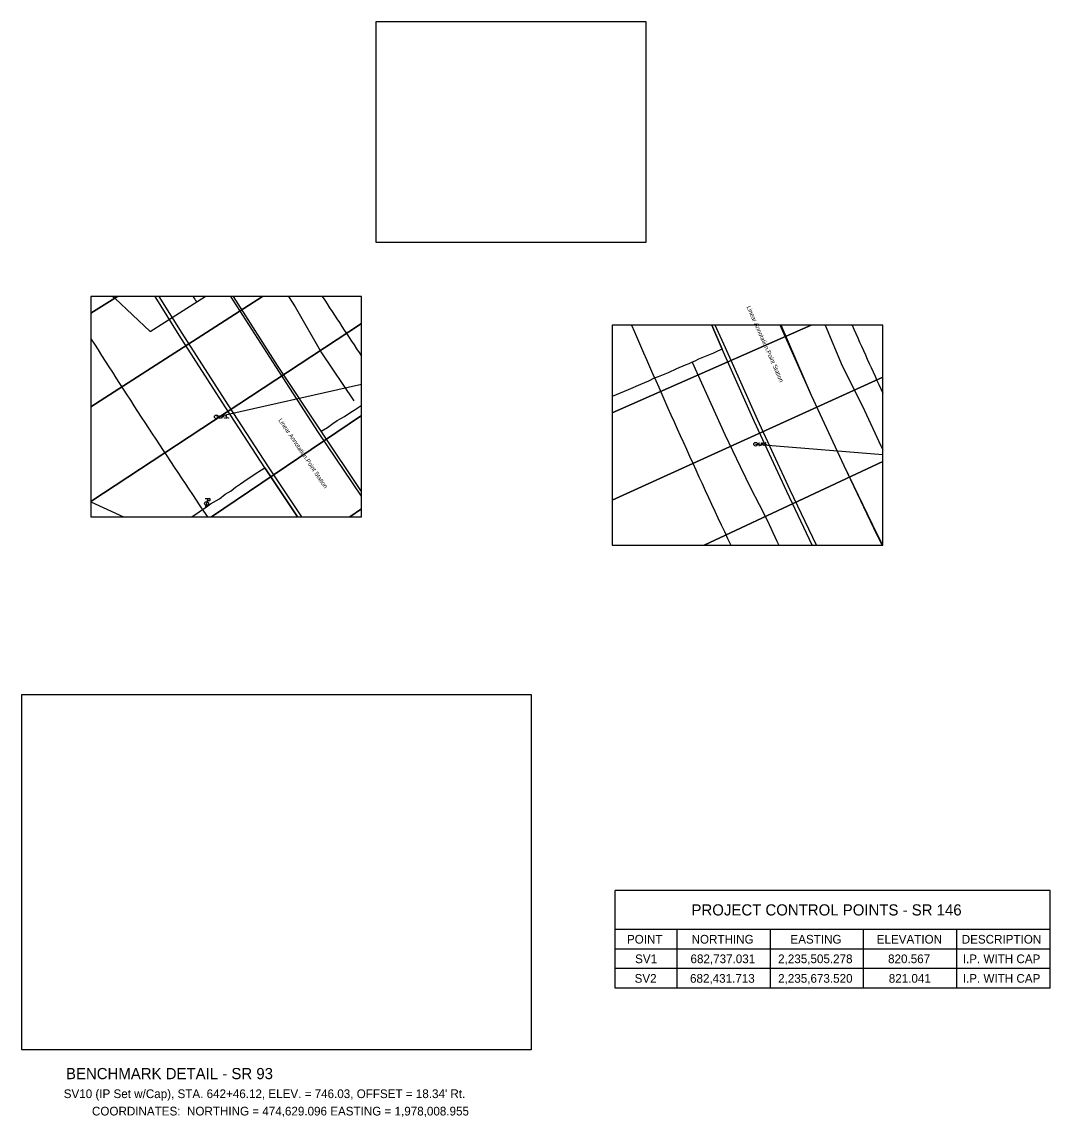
# Model space of a CAD drawing. Extents: x 0 to 2009, y -63 to 801.
# Drawn here: x 305.4 to 636.3, y 448.3 to 801 of the extents above; entities that cross this region are included whole.
import ezdxf

# ---------------------------------------------------------------- set-up
doc = ezdxf.new("R2010")
doc.units = 0
for name, color, linetype in [('Default', 7, 'Continuous'), ('DR_X_Ditch', 7, 'Continuous'), ('GE_P_Alignment', 7, 'Continuous'), ('GE_X_Alignment', 7, 'Continuous'), ('GE_X_Cells', 7, 'Continuous'), ('PF_P_Sta_Elev_Text', 7, 'Continuous'), ('PF_X_Text', 7, 'Continuous'), ('PV_X_Driveway', 7, 'Continuous'), ('RD_P_Cells', 7, 'Continuous'), ('RW_X_CL_100_Stations', 7, 'Continuous'), ('RW_X_CL_500_Stations', 7, 'Continuous'), ('SH_Data', 7, 'Continuous'), ('SN_X_Public', 7, 'Continuous'), ('ST_Text', 7, 'Continuous'), ('SV_P_Control_Cells_Set', 7, 'Continuous'), ('SV_X_Text_Name', 7, 'Continuous'), ('TX_P_1', 7, 'Continuous'), ('TX_P_Misc', 7, 'Continuous'), ('UT_X_Telecom', 7, 'Continuous'), ('XS_P_Finished_Grade', 7, 'Continuous'), ('XS_P_Pavt_Surface', 7, 'Continuous')]:
    doc.layers.add(name, color=color, linetype=linetype)

msp = doc.modelspace()

# ---------------------------------------------------------------- linework, layer by layer
at = {"layer": 'DR_X_Ditch'}
msp.add_lwpolyline([(305.36, 584.42), (469.27, 584.42), (469.27, 469.95), (305.36, 469.95)], close=True, dxfattribs=at)
at = {"layer": 'GE_P_Alignment'}
for points in [[(394.06, 641.65), (383.49, 657.42), (369.82, 678.5), (355.95, 700.12), (348.27, 712.56)], [(414.66, 649.71), (401.63, 669.22), (387.65, 690.38), (374.21, 711.42), (373.48, 712.56)], [(559.68, 632.46), (551.57, 649.72), (541.01, 672.42), (530.76, 695.62), (527.41, 703.37)], [(582.41, 632.49), (580.75, 635.83), (569.94, 658.08), (559.48, 680.72), (549.69, 703.37)]]:
    msp.add_lwpolyline(points, dxfattribs=at)
at = {"layer": 'GE_X_Alignment'}
for p, q in [((365.22, 647.48), (364.42, 644.48)), ((365.05, 646.84), (365.64, 646.84)), ((365.22, 647.48), (365.64, 647.48))]:
    msp.add_line(p, q, dxfattribs=at)
msp.add_circle((364.79, 645.88), 0.65, dxfattribs=at)
msp.add_arc((365.65, 647.16), 0.319, 268.8767, 91.1233, dxfattribs=at)
at = {"layer": 'GE_X_Cells'}
for p, q in [((496.25, 489.85), (496.25, 521.35)), ((636.25, 521.35), (496.25, 521.35)), ((636.25, 489.85), (636.25, 521.35)), ((636.25, 508.75), (496.25, 508.75)), ((516.25, 489.85), (516.25, 508.75)), ((546.25, 489.85), (546.25, 508.75)), ((576.25, 489.85), (576.25, 508.75)), ((606.25, 489.85), (606.25, 508.75)), ((636.25, 502.45), (496.25, 502.45)), ((636.25, 496.15), (496.25, 496.15)), ((636.25, 489.85), (496.25, 489.85))]:
    msp.add_line(p, q, dxfattribs=at)
at = {"layer": 'PF_P_Sta_Elev_Text'}
for points in [[(368.95, 674.17), (369.13, 674.17)], [(368.95, 674.17), (369.13, 674.17)], [(369.04, 673.37), (369.04, 674.17)], [(369.04, 673.37), (369.04, 674.17)], [(369.82, 673.37), (369.82, 674.17), (370.09, 674.17), (370.11, 674.16), (370.15, 674.15), (370.17, 674.14), (370.19, 674.13), (370.21, 674.1), (370.22, 674.06), (370.24, 674.01), (370.24, 673.94), (370.23, 673.91), (370.22, 673.88), (370.2, 673.83), (370.18, 673.81), (370.16, 673.8), (370.13, 673.79), (370.09, 673.78), (369.82, 673.78)], [(369.82, 673.37), (369.82, 674.17), (370.09, 674.17), (370.11, 674.16), (370.15, 674.15), (370.17, 674.14), (370.19, 674.13), (370.21, 674.1), (370.22, 674.06), (370.24, 674.01), (370.24, 673.94), (370.23, 673.91), (370.22, 673.88), (370.2, 673.83), (370.18, 673.81), (370.16, 673.8), (370.13, 673.79), (370.09, 673.78), (369.82, 673.78)], [(371.33, 674.11), (371.32, 674.13), (371.3, 674.14), (371.25, 674.16), (371.19, 674.17), (371.15, 674.17), (371.13, 674.17), (371.06, 674.15), (371, 674.11), (370.96, 674.06), (370.95, 674.01), (370.95, 673.98), (370.96, 673.93), (371, 673.88), (371.31, 673.69), (371.33, 673.67), (371.34, 673.64), (371.35, 673.6), (371.35, 673.57), (371.35, 673.53), (371.34, 673.5), (371.33, 673.47), (371.32, 673.45), (371.31, 673.43), (371.29, 673.41), (371.28, 673.4), (371.26, 673.38), (371.24, 673.38), (371.19, 673.37), (371.11, 673.37), (371.06, 673.38), (370.99, 673.43), (370.95, 673.47)], [(371.33, 674.11), (371.32, 674.13), (371.3, 674.14), (371.25, 674.16), (371.19, 674.17), (371.15, 674.17), (371.13, 674.17), (371.06, 674.15), (371, 674.11), (370.96, 674.06), (370.95, 674.01), (370.95, 673.98), (370.96, 673.93), (371, 673.88), (371.31, 673.69), (371.33, 673.67), (371.34, 673.64), (371.35, 673.6), (371.35, 673.57), (371.35, 673.53), (371.34, 673.5), (371.33, 673.47), (371.32, 673.45), (371.31, 673.43), (371.29, 673.41), (371.28, 673.4), (371.26, 673.38), (371.24, 673.38), (371.19, 673.37), (371.11, 673.37), (371.06, 673.38), (370.99, 673.43), (370.95, 673.47)], [(368.95, 673.37), (369.13, 673.37)], [(368.95, 673.37), (369.13, 673.37)], [(369.52, 673.48), (369.55, 673.48), (369.56, 673.47), (369.58, 673.44), (369.58, 673.41), (369.56, 673.38), (369.55, 673.37), (369.52, 673.37), (369.5, 673.38), (369.49, 673.41), (369.49, 673.44), (369.5, 673.47), (369.52, 673.48)], [(369.52, 673.48), (369.55, 673.48), (369.56, 673.47), (369.58, 673.44), (369.58, 673.41), (369.56, 673.38), (369.55, 673.37), (369.52, 673.37), (369.5, 673.38), (369.49, 673.41), (369.49, 673.44), (369.5, 673.47), (369.52, 673.48)], [(370.64, 673.48), (370.67, 673.48), (370.69, 673.47), (370.7, 673.44), (370.7, 673.41), (370.69, 673.38), (370.67, 673.37), (370.64, 673.37), (370.63, 673.38), (370.61, 673.41), (370.61, 673.44), (370.63, 673.47), (370.64, 673.48)], [(370.64, 673.48), (370.67, 673.48), (370.69, 673.47), (370.7, 673.44), (370.7, 673.41), (370.69, 673.38), (370.67, 673.37), (370.64, 673.37), (370.63, 673.38), (370.61, 673.41), (370.61, 673.44), (370.63, 673.47), (370.64, 673.48)], [(371.73, 673.48), (371.76, 673.48), (371.78, 673.47), (371.8, 673.44), (371.8, 673.41), (371.78, 673.38), (371.76, 673.37), (371.73, 673.37), (371.72, 673.38), (371.7, 673.41), (371.7, 673.44), (371.72, 673.47), (371.73, 673.48)], [(371.73, 673.48), (371.76, 673.48), (371.78, 673.47), (371.8, 673.44), (371.8, 673.41), (371.78, 673.38), (371.76, 673.37), (371.73, 673.37), (371.72, 673.38), (371.7, 673.41), (371.7, 673.44), (371.72, 673.47), (371.73, 673.48)], [(542.51, 665.38), (542.69, 665.38)], [(542.51, 665.38), (542.69, 665.38)], [(542.51, 664.58), (542.69, 664.58)], [(542.51, 664.58), (542.69, 664.58)], [(542.6, 664.58), (542.6, 665.38)], [(542.6, 664.58), (542.6, 665.38)], [(543.08, 664.69), (543.11, 664.69), (543.12, 664.67), (543.14, 664.65), (543.14, 664.62), (543.12, 664.59), (543.11, 664.58), (543.08, 664.58), (543.06, 664.59), (543.05, 664.62), (543.05, 664.65), (543.06, 664.67), (543.08, 664.69)], [(543.08, 664.69), (543.11, 664.69), (543.12, 664.67), (543.14, 664.65), (543.14, 664.62), (543.12, 664.59), (543.11, 664.58), (543.08, 664.58), (543.06, 664.59), (543.05, 664.62), (543.05, 664.65), (543.06, 664.67), (543.08, 664.69)], [(543.38, 664.58), (543.38, 665.38), (543.65, 665.38), (543.68, 665.37), (543.71, 665.36), (543.73, 665.35), (543.75, 665.33), (543.77, 665.3), (543.79, 665.27), (543.8, 665.22), (543.8, 665.15), (543.79, 665.12), (543.78, 665.08), (543.76, 665.04), (543.74, 665.02), (543.72, 665.01), (543.69, 664.99), (543.65, 664.99), (543.38, 664.99)], [(543.38, 664.58), (543.38, 665.38), (543.65, 665.38), (543.68, 665.37), (543.71, 665.36), (543.73, 665.35), (543.75, 665.33), (543.77, 665.3), (543.79, 665.27), (543.8, 665.22), (543.8, 665.15), (543.79, 665.12), (543.78, 665.08), (543.76, 665.04), (543.74, 665.02), (543.72, 665.01), (543.69, 664.99), (543.65, 664.99), (543.38, 664.99)], [(544.2, 664.69), (544.23, 664.69), (544.25, 664.67), (544.27, 664.65), (544.27, 664.62), (544.25, 664.59), (544.23, 664.58), (544.2, 664.58), (544.19, 664.59), (544.17, 664.62), (544.17, 664.65), (544.19, 664.67), (544.2, 664.69)], [(544.2, 664.69), (544.23, 664.69), (544.25, 664.67), (544.27, 664.65), (544.27, 664.62), (544.25, 664.59), (544.23, 664.58), (544.2, 664.58), (544.19, 664.59), (544.17, 664.62), (544.17, 664.65), (544.19, 664.67), (544.2, 664.69)], [(544.89, 665.32), (544.88, 665.33), (544.86, 665.35), (544.81, 665.37), (544.75, 665.38), (544.71, 665.38), (544.69, 665.38), (544.62, 665.36), (544.56, 665.32), (544.52, 665.27), (544.51, 665.22), (544.51, 665.18), (544.52, 665.13), (544.56, 665.09), (544.87, 664.9), (544.89, 664.87), (544.9, 664.85), (544.92, 664.81), (544.92, 664.77), (544.91, 664.74), (544.9, 664.71), (544.89, 664.68), (544.88, 664.65), (544.87, 664.64), (544.86, 664.62), (544.84, 664.6), (544.82, 664.59), (544.8, 664.58), (544.75, 664.58), (544.67, 664.58), (544.62, 664.59), (544.55, 664.64), (544.51, 664.67)], [(544.89, 665.32), (544.88, 665.33), (544.86, 665.35), (544.81, 665.37), (544.75, 665.38), (544.71, 665.38), (544.69, 665.38), (544.62, 665.36), (544.56, 665.32), (544.52, 665.27), (544.51, 665.22), (544.51, 665.18), (544.52, 665.13), (544.56, 665.09), (544.87, 664.9), (544.89, 664.87), (544.9, 664.85), (544.92, 664.81), (544.92, 664.77), (544.91, 664.74), (544.9, 664.71), (544.89, 664.68), (544.88, 664.65), (544.87, 664.64), (544.86, 664.62), (544.84, 664.6), (544.82, 664.59), (544.8, 664.58), (544.75, 664.58), (544.67, 664.58), (544.62, 664.59), (544.55, 664.64), (544.51, 664.67)], [(545.3, 664.69), (545.32, 664.69), (545.34, 664.67), (545.36, 664.65), (545.36, 664.62), (545.34, 664.59), (545.32, 664.58), (545.3, 664.58), (545.28, 664.59), (545.26, 664.62), (545.26, 664.65), (545.28, 664.67), (545.3, 664.69)], [(545.3, 664.69), (545.32, 664.69), (545.34, 664.67), (545.36, 664.65), (545.36, 664.62), (545.34, 664.59), (545.32, 664.58), (545.3, 664.58), (545.28, 664.59), (545.26, 664.62), (545.26, 664.65), (545.28, 664.67), (545.3, 664.69)]]:
    msp.add_lwpolyline(points, dxfattribs=at)
for centre in [(367.94, 673.77), (367.94, 673.77), (541.5, 664.98), (541.5, 664.98)]:
    msp.add_circle(centre, 0.6, dxfattribs=at)
at = {"layer": 'PF_X_Text'}
for points in [[(395.4, 641.65), (384.53, 658.06), (370.8, 679.15), (356.98, 700.71), (349.58, 712.56)], [(414.66, 648.15), (414.62, 648.21), (400.85, 668.8), (387.03, 690.02), (373.56, 711.02), (372.6, 712.56)], [(561.03, 632.46), (552.65, 650.14), (542.12, 672.9), (531.74, 696.02), (528.52, 703.37)], [(582.2, 632.46), (580.59, 635.73), (569.94, 658.08), (559.48, 680.72), (549.35, 703.37)]]:
    msp.add_lwpolyline(points, dxfattribs=at)
at = {"layer": 'RD_P_Cells'}
for points in [[(391.13, 712.56), (393.27, 709.19), (401.8, 694.46), (412.21, 678.92)], [(563.83, 703.37), (569.35, 690.2), (575.9, 677.28), (581.77, 664.49), (582.41, 663.15)]]:
    msp.add_lwpolyline(points, dxfattribs=at)
at = {"layer": 'RW_X_CL_100_Stations'}
for p, q in [((327.59, 707.2), (336.13, 712.56)), ((336.13, 712.56), (327.59, 707.2)), ((327.59, 677.06), (382.75, 712.56)), ((382.75, 712.56), (327.59, 677.06)), ((327.59, 707.2), (336.13, 712.56)), ((336.13, 712.56), (327.59, 707.2)), ((327.59, 677.06), (382.75, 712.56)), ((382.75, 712.56), (327.59, 677.06)), ((336.13, 712.56), (336.13, 712.56)), ((336.13, 712.56), (336.13, 712.56)), ((382.75, 712.56), (382.75, 712.56)), ((382.75, 712.56), (382.75, 712.56)), ((327.59, 707.2), (327.59, 707.2)), ((327.59, 707.2), (327.59, 707.2)), ((327.59, 646.5), (414.66, 703.9)), ((414.66, 703.9), (327.59, 646.5)), ((327.59, 646.5), (414.66, 703.9)), ((414.66, 703.9), (327.59, 646.5)), ((414.66, 703.9), (414.66, 703.9)), ((414.66, 703.9), (414.66, 703.9)), ((495.34, 675.06), (559.36, 703.37)), ((559.36, 703.37), (495.34, 675.06)), ((495.34, 675.06), (559.36, 703.37)), ((559.36, 703.37), (495.34, 675.06)), ((559.36, 703.37), (559.36, 703.37)), ((559.36, 703.37), (559.36, 703.37)), ((495.34, 646.95), (582.41, 686.62)), ((582.41, 686.62), (495.34, 646.95)), ((495.34, 646.95), (582.41, 686.62)), ((582.41, 686.62), (495.34, 646.95)), ((582.41, 686.62), (582.41, 686.62)), ((582.41, 686.62), (582.41, 686.62)), ((327.59, 677.06), (327.59, 677.06)), ((327.59, 677.06), (327.59, 677.06)), ((366.33, 641.65), (414.66, 674.28)), ((414.66, 674.28), (366.33, 641.65)), ((366.33, 641.65), (414.66, 674.28)), ((414.66, 674.28), (366.33, 641.65)), ((414.66, 674.28), (414.66, 674.28)), ((414.66, 674.28), (414.66, 674.28)), ((495.34, 675.06), (495.34, 675.06)), ((495.34, 675.06), (495.34, 675.06)), ((524.97, 632.46), (582.41, 659.4)), ((582.41, 659.4), (524.97, 632.46)), ((524.97, 632.46), (582.41, 659.4)), ((582.41, 659.4), (524.97, 632.46)), ((582.41, 659.4), (582.41, 659.4)), ((582.41, 659.4), (582.41, 659.4)), ((327.59, 646.5), (327.59, 646.5)), ((327.59, 646.5), (327.59, 646.5)), ((495.34, 646.95), (495.34, 646.95)), ((495.34, 646.95), (495.34, 646.95)), ((410.94, 641.65), (414.66, 644.22)), ((414.66, 644.22), (410.94, 641.65)), ((414.66, 644.22), (414.66, 644.22)), ((366.33, 641.65), (366.33, 641.65)), ((366.33, 641.65), (366.33, 641.65)), ((410.94, 641.65), (410.94, 641.65)), ((524.97, 632.46), (524.97, 632.46)), ((524.97, 632.46), (524.97, 632.46))]:
    msp.add_line(p, q, dxfattribs=at)
at = {"layer": 'RW_X_CL_500_Stations'}
for p, q in [((334.62, 712.56), (335.23, 711.99)), ((346.63, 701.3), (364.29, 712.56)), ((335.23, 711.99), (346.63, 701.3))]:
    msp.add_line(p, q, dxfattribs=at)
at = {"layer": 'SN_X_Public'}
for p, q in [((367.94, 673.77), (414.66, 684.34)), ((541.5, 664.98), (582.41, 661.66))]:
    msp.add_line(p, q, dxfattribs=at)
for points in [[(419.22, 730.05), (506.29, 730.05), (506.29, 800.96), (419.22, 800.96)], [(414.66, 712.56), (327.59, 712.56), (327.59, 641.65), (414.66, 641.65)], [(582.41, 703.37), (495.34, 703.37), (495.34, 632.46), (582.41, 632.46)]]:
    msp.add_lwpolyline(points, close=True, dxfattribs=at)
at = {"layer": 'ST_Text'}
msp.add_line((327.59, 646.43), (338.03, 641.65), dxfattribs=at)
for points in [[(527.41, 703.37), (530.76, 695.62), (529.19, 694.95), (527.95, 694.29), (523.13, 692.32), (521.93, 691.75), (521.04, 691.4), (520.03, 690.86), (518.79, 690.41), (516.02, 689.25), (513.35, 687.98), (510.13, 686.71), (508.88, 686.21), (507, 685.27), (504.39, 684.2), (500.44, 682.49), (495.34, 680.3)], [(414.66, 649.71), (401.63, 669.22), (403.68, 670.4), (405.39, 671.67), (406.77, 672.59), (409.15, 673.94), (411.23, 675.28), (412.34, 675.98), (414.23, 677.2), (414.66, 677.47)], [(360.04, 641.65), (364.78, 644.79), (366.01, 645.75), (368.94, 647.43), (370.79, 648.89), (372.68, 649.98), (374.09, 651.17), (375.74, 652.23), (376.76, 652.94), (380.46, 655.44), (382.5, 656.72), (383.49, 657.42), (394.06, 641.65)]]:
    msp.add_lwpolyline(points, dxfattribs=at)
at = {"layer": 'SV_X_Text_Name'}
msp.add_arc((2260.39, 1920.83), 2251.63, 212.45411, 212.50711, dxfattribs=at)
at = {"layer": 'TX_P_1'}
for centre, radius, start, end in [((2260.39, 1920.83), 2216.63, 213.0313, 213.62545), ((2602.19, 1606.72), 2286.63, 203.26967, 205.21842), ((2602.19, 1606.72), 2221.63, 203.99255, 204.61261), ((2260.39, 1920.83), 2286.63, 212.29987, 214.01577)]:
    msp.add_arc(centre, radius, start, end, dxfattribs=at)
at = {"layer": 'TX_P_Misc'}
for p, q in [((366.93, 702.38), (367.43, 702.7)), ((542.92, 696.1), (543.84, 696.51)), ((394.45, 660.64), (395.28, 661.2)), ((563.65, 650.6), (564.19, 650.86))]:
    msp.add_line(p, q, dxfattribs=at)
at = {"layer": 'UT_X_Telecom'}
msp.add_lwpolyline([(521.04, 691.4), (531.59, 668.11), (536.47, 657.82), (539.95, 650.76), (542.64, 645.59), (545.24, 640.48), (548.33, 633.77), (548.92, 632.46)], dxfattribs=at)
at = {"layer": 'XS_P_Finished_Grade'}
msp.add_line((414.54, 641.65), (414.66, 641.73), dxfattribs=at)
at = {"layer": 'XS_P_Pavt_Surface'}
for p, q in [((365.99, 647.38), (364.39, 647.38)), ((365.19, 647.38), (364.39, 644.38))]:
    msp.add_line(p, q, dxfattribs=at)
msp.add_circle((364.79, 645.88), 0.65, dxfattribs=at)

# ---------------------------------------------------------------- texts
at = {"layer": 'Default'}
for s, p in [('POINT', (500.08, 504.2)), ('NORTHING', (520.88, 504.2)), ('EASTING', (552.69, 504.2)), ('ELEVATION', (580.46, 504.2)), ('DESCRIPTION', (607.82, 504.2)), ('SV1', (502.7, 497.9)), ('682,737.031', (520.53, 497.9)), ('2,235,505.278', (548.73, 497.9)), ('820.567', (584.11, 497.9)), ('I.P. WITH CAP', (608.15, 497.9)), ('SV2', (502.54, 491.6)), ('682,431.713', (520.38, 491.6)), ('2,235,673.520', (548.73, 491.6)), ('821.041', (584.33, 491.6)), ('I.P. WITH CAP', (608.15, 491.6))]:
    msp.add_text(s, height=2.8, dxfattribs=at).set_placement(p)
at = {"layer": 'PV_X_Driveway'}
for s, p in [("SV10 (IP Set w/Cap), STA. 642+46.12, ELEV. = 746.03, OFFSET = 18.34' Rt.", (318.82, 454.46)), ('COORDINATES:  NORTHING = 474,629.096 EASTING = 1,978,008.955', (327.91, 448.86))]:
    msp.add_text(s, height=2.8, dxfattribs=at).set_placement(p)
at = {"layer": 'SH_Data'}
msp.add_text('PROJECT CONTROL POINTS - SR 146', height=3.6, dxfattribs=at).set_placement((520.85, 513.25))
at = {"layer": 'SV_P_Control_Cells_Set'}
msp.add_text('BENCHMARK DETAIL - SR 93', height=3.6, dxfattribs=at).set_placement((319.55, 460.55))
at = {"layer": 'TX_P_Misc'}
for rotation, p in [(293.8553, (538.52, 709.16)), (304.0339, (387.81, 672.71))]:
    msp.add_text('Linear Annotation.Point Station', height=1.4, rotation=rotation, dxfattribs=at).set_placement(p)

doc.saveas('drawing.dxf')
